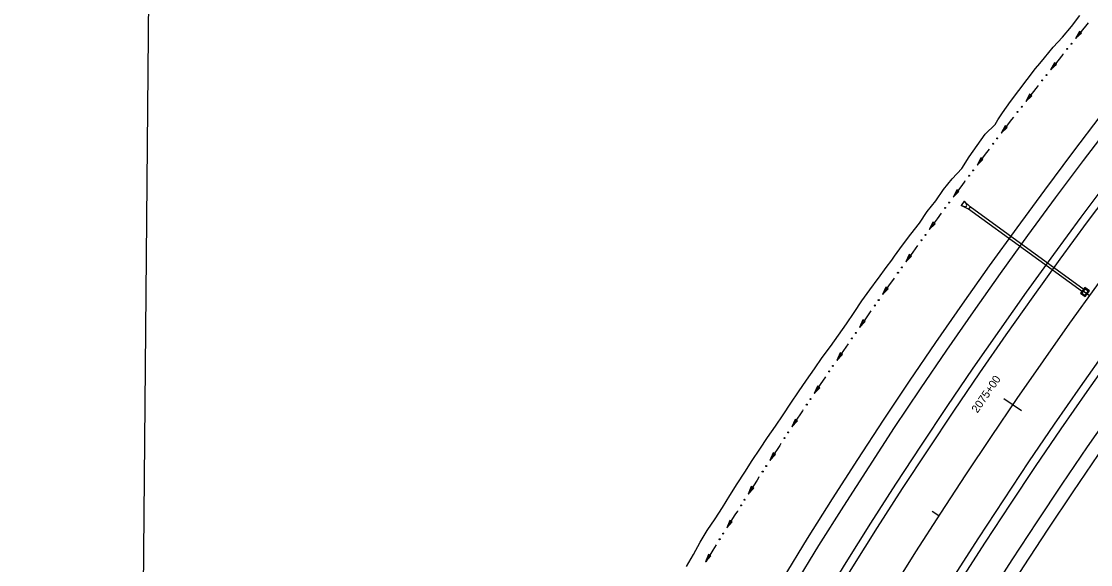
# Model space of a CAD drawing. Extents: x 1611108 to 1749517, y 619561 to 797725.
# Drawn here: x 1713533 to 1714335, y 764266 to 764673 of the extents above; entities that cross this region are included whole.
import ezdxf

# ---------------------------------------------------------------- set-up
doc = ezdxf.new("R2010")
doc.units = 0
for name, color, linetype in [('R_Ditch', 7, 'Continuous'), ('R_Drainage', 7, 'Continuous'), ('R_Horz Alg', 7, 'Continuous'), ('R_Horz Alg Annot', 7, 'Continuous'), ('R_Horz Alg Stationing', 7, 'Continuous'), ('R_Proposed Const Limits', 7, 'Continuous'), ('R_Proposed Road', 7, 'Continuous')]:
    doc.layers.add(name, color=color, linetype=linetype)

msp = doc.modelspace()

# ---------------------------------------------------------------- linework, layer by layer
at = {"layer": 'R_Ditch'}
for p, q in [((1714326.16, 764665.53), (1714323.23, 764660.19)), ((1714326.16, 764665.53), (1714323.23, 764660.19)), ((1714323.23, 764660.19), (1714327.81, 764664.21)), ((1714323.23, 764660.19), (1714327.81, 764664.21)), ((1714327.81, 764664.21), (1714326.16, 764665.53)), ((1714327.81, 764664.21), (1714326.16, 764665.53)), ((1714307.4, 764642.07), (1714304.51, 764636.7)), ((1714307.4, 764642.07), (1714304.51, 764636.7)), ((1714304.51, 764636.7), (1714309.06, 764640.75)), ((1714304.51, 764636.7), (1714309.06, 764640.75)), ((1714309.06, 764640.75), (1714307.4, 764642.07)), ((1714309.06, 764640.75), (1714307.4, 764642.07)), ((1714288.81, 764618.46), (1714285.97, 764613.07)), ((1714288.81, 764618.46), (1714285.97, 764613.07)), ((1714290.48, 764617.16), (1714288.81, 764618.46)), ((1714290.48, 764617.16), (1714288.81, 764618.46)), ((1714285.97, 764613.07), (1714290.48, 764617.16)), ((1714285.97, 764613.07), (1714290.48, 764617.16)), ((1714270.42, 764594.7), (1714267.6, 764589.3)), ((1714270.42, 764594.7), (1714267.6, 764589.3)), ((1714272.09, 764593.41), (1714270.42, 764594.7)), ((1714272.09, 764593.41), (1714270.42, 764594.7)), ((1714267.6, 764589.3), (1714272.09, 764593.41)), ((1714267.6, 764589.3), (1714272.09, 764593.41)), ((1714252.2, 764570.81), (1714249.42, 764565.39)), ((1714252.2, 764570.81), (1714249.42, 764565.39)), ((1714253.88, 764569.54), (1714252.2, 764570.81)), ((1714253.88, 764569.54), (1714252.2, 764570.81)), ((1714249.42, 764565.39), (1714253.88, 764569.54)), ((1714249.42, 764565.39), (1714253.88, 764569.54)), ((1714234.16, 764546.79), (1714231.42, 764541.34)), ((1714234.16, 764546.79), (1714231.42, 764541.34)), ((1714235.85, 764545.52), (1714234.16, 764546.79)), ((1714235.85, 764545.52), (1714234.16, 764546.79)), ((1714231.42, 764541.34), (1714235.85, 764545.52)), ((1714231.42, 764541.34), (1714235.85, 764545.52)), ((1714216.3, 764522.62), (1714213.61, 764517.16)), ((1714216.3, 764522.62), (1714213.61, 764517.16)), ((1714218.01, 764521.37), (1714216.3, 764522.62)), ((1714218.01, 764521.37), (1714216.3, 764522.62)), ((1714213.61, 764517.16), (1714218.01, 764521.37)), ((1714213.61, 764517.16), (1714218.01, 764521.37)), ((1714198.63, 764498.32), (1714195.98, 764492.84)), ((1714198.63, 764498.32), (1714195.98, 764492.84)), ((1714200.35, 764497.08), (1714198.63, 764498.32)), ((1714200.35, 764497.08), (1714198.63, 764498.32)), ((1714195.98, 764492.84), (1714200.35, 764497.08)), ((1714195.98, 764492.84), (1714200.35, 764497.08)), ((1714181.14, 764473.89), (1714178.54, 764468.38)), ((1714181.14, 764473.89), (1714178.54, 764468.38)), ((1714178.54, 764468.38), (1714182.87, 764472.66)), ((1714178.54, 764468.38), (1714182.87, 764472.66)), ((1714182.87, 764472.66), (1714181.14, 764473.89)), ((1714182.87, 764472.66), (1714181.14, 764473.89)), ((1714163.84, 764449.32), (1714161.28, 764443.8)), ((1714163.84, 764449.32), (1714161.28, 764443.8)), ((1714161.28, 764443.8), (1714165.58, 764448.11)), ((1714161.28, 764443.8), (1714165.58, 764448.11)), ((1714165.58, 764448.11), (1714163.84, 764449.32)), ((1714165.58, 764448.11), (1714163.84, 764449.32)), ((1714146.73, 764424.63), (1714144.21, 764419.08)), ((1714146.73, 764424.63), (1714144.21, 764419.08)), ((1714144.21, 764419.08), (1714148.47, 764423.43)), ((1714144.21, 764419.08), (1714148.47, 764423.43)), ((1714148.47, 764423.43), (1714146.73, 764424.63)), ((1714148.47, 764423.43), (1714146.73, 764424.63)), ((1714129.8, 764399.8), (1714127.33, 764394.23)), ((1714129.8, 764399.8), (1714127.33, 764394.23)), ((1714127.33, 764394.23), (1714131.56, 764398.62)), ((1714127.33, 764394.23), (1714131.56, 764398.62)), ((1714131.56, 764398.62), (1714129.8, 764399.8)), ((1714131.56, 764398.62), (1714129.8, 764399.8)), ((1714113.07, 764374.85), (1714110.64, 764369.26)), ((1714113.07, 764374.85), (1714110.64, 764369.26)), ((1714110.64, 764369.26), (1714114.83, 764373.68)), ((1714110.64, 764369.26), (1714114.83, 764373.68)), ((1714114.83, 764373.68), (1714113.07, 764374.85)), ((1714114.83, 764373.68), (1714113.07, 764374.85)), ((1714096.53, 764349.76), (1714094.14, 764344.16)), ((1714096.53, 764349.76), (1714094.14, 764344.16)), ((1714094.14, 764344.16), (1714098.3, 764348.61)), ((1714094.14, 764344.16), (1714098.3, 764348.61)), ((1714098.3, 764348.61), (1714096.53, 764349.76)), ((1714098.3, 764348.61), (1714096.53, 764349.76)), ((1714080.2, 764324.54), (1714077.85, 764318.92)), ((1714080.2, 764324.54), (1714077.85, 764318.92)), ((1714077.85, 764318.92), (1714081.98, 764323.4)), ((1714077.85, 764318.92), (1714081.98, 764323.4)), ((1714081.98, 764323.4), (1714080.2, 764324.54)), ((1714081.98, 764323.4), (1714080.2, 764324.54)), ((1714064.07, 764299.19), (1714061.77, 764293.55)), ((1714064.07, 764299.19), (1714061.77, 764293.55)), ((1714061.77, 764293.55), (1714065.86, 764298.06)), ((1714061.77, 764293.55), (1714065.86, 764298.06)), ((1714065.86, 764298.06), (1714064.07, 764299.19)), ((1714065.86, 764298.06), (1714064.07, 764299.19)), ((1714048.15, 764273.71), (1714045.89, 764268.05)), ((1714048.15, 764273.71), (1714045.89, 764268.05)), ((1714049.95, 764272.6), (1714048.15, 764273.71)), ((1714049.95, 764272.6), (1714048.15, 764273.71)), ((1714045.89, 764268.05), (1714049.95, 764272.6)), ((1714045.89, 764268.05), (1714049.95, 764272.6))]:
    msp.add_line(p, q, dxfattribs=at)
for points in [[(1714332.64, 764671.87), (1714326.52, 764664.29), (1714323.23, 764660.19)], [(1714332.64, 764671.87), (1714326.52, 764664.29), (1714323.23, 764660.19)], [(1714332.67, 764671.9), (1714332.64, 764671.87)], [(1714332.67, 764671.9), (1714332.64, 764671.87)], [(1714313.83, 764648.45), (1714313.61, 764648.17), (1714307.18, 764640.08), (1714304.51, 764636.7)], [(1714313.83, 764648.45), (1714313.61, 764648.17), (1714307.18, 764640.08), (1714304.51, 764636.7)], [(1714313.86, 764648.48), (1714313.83, 764648.45)], [(1714313.86, 764648.48), (1714313.83, 764648.45)], [(1714295.2, 764624.89), (1714294.39, 764623.86), (1714288.03, 764615.73), (1714285.97, 764613.07)], [(1714295.2, 764624.89), (1714294.39, 764623.86), (1714288.03, 764615.73), (1714285.97, 764613.07)], [(1714295.22, 764624.92), (1714295.2, 764624.89)], [(1714295.22, 764624.92), (1714295.2, 764624.89)], [(1714276.75, 764601.19), (1714275.37, 764599.41), (1714269.07, 764591.22), (1714267.6, 764589.3)], [(1714276.75, 764601.19), (1714275.37, 764599.41), (1714269.07, 764591.22), (1714267.6, 764589.3)], [(1714276.77, 764601.22), (1714276.75, 764601.19)], [(1714276.77, 764601.22), (1714276.75, 764601.19)], [(1714258.48, 764577.35), (1714256.54, 764574.8), (1714250.3, 764566.56), (1714249.42, 764565.39)], [(1714258.48, 764577.35), (1714256.54, 764574.8), (1714250.3, 764566.56), (1714249.42, 764565.39)], [(1714258.5, 764577.38), (1714258.48, 764577.35)], [(1714258.5, 764577.38), (1714258.48, 764577.35)], [(1714240.39, 764553.37), (1714237.9, 764550.04), (1714231.73, 764541.75), (1714231.42, 764541.34)], [(1714240.39, 764553.37), (1714237.9, 764550.04), (1714231.73, 764541.75), (1714231.42, 764541.34)], [(1714240.41, 764553.4), (1714240.39, 764553.37)], [(1714240.41, 764553.4), (1714240.39, 764553.37)], [(1714222.48, 764529.25), (1714219.45, 764525.13), (1714213.61, 764517.16)], [(1714222.48, 764529.25), (1714219.45, 764525.13), (1714213.61, 764517.16)], [(1714222.51, 764529.28), (1714222.48, 764529.25)], [(1714222.51, 764529.28), (1714222.48, 764529.25)], [(1714204.76, 764505), (1714201.2, 764500.08), (1714195.98, 764492.84)], [(1714204.76, 764505), (1714201.2, 764500.08), (1714195.98, 764492.84)], [(1714204.78, 764505.03), (1714204.76, 764505)], [(1714204.78, 764505.03), (1714204.76, 764505)], [(1714187.22, 764480.61), (1714183.14, 764474.88), (1714178.54, 764468.38)], [(1714187.22, 764480.61), (1714183.14, 764474.88), (1714178.54, 764468.38)], [(1714187.25, 764480.64), (1714187.22, 764480.61)], [(1714187.25, 764480.64), (1714187.22, 764480.61)], [(1714169.87, 764456.09), (1714165.29, 764449.54), (1714161.28, 764443.8)], [(1714169.87, 764456.09), (1714165.29, 764449.54), (1714161.28, 764443.8)], [(1714169.89, 764456.12), (1714169.87, 764456.09)], [(1714169.89, 764456.12), (1714169.87, 764456.09)], [(1714152.71, 764431.44), (1714147.62, 764424.06), (1714144.21, 764419.08)], [(1714152.71, 764431.44), (1714147.62, 764424.06), (1714144.21, 764419.08)], [(1714152.73, 764431.47), (1714152.71, 764431.44)], [(1714152.73, 764431.47), (1714152.71, 764431.44)], [(1714135.73, 764406.66), (1714130.16, 764398.44), (1714127.33, 764394.23)], [(1714135.73, 764406.66), (1714130.16, 764398.44), (1714127.33, 764394.23)], [(1714135.75, 764406.69), (1714135.73, 764406.66)], [(1714135.75, 764406.69), (1714135.73, 764406.66)], [(1714118.95, 764381.75), (1714118.63, 764381.28), (1714112.9, 764372.68), (1714110.64, 764369.26)], [(1714118.95, 764381.75), (1714118.63, 764381.28), (1714112.9, 764372.68), (1714110.64, 764369.26)], [(1714118.97, 764381.78), (1714118.95, 764381.75)], [(1714118.97, 764381.78), (1714118.95, 764381.75)], [(1714102.35, 764356.71), (1714101.51, 764355.43), (1714095.85, 764346.78), (1714094.14, 764344.16)], [(1714102.35, 764356.71), (1714101.51, 764355.43), (1714095.85, 764346.78), (1714094.14, 764344.16)], [(1714102.37, 764356.74), (1714102.35, 764356.71)], [(1714102.37, 764356.74), (1714102.35, 764356.71)], [(1714085.96, 764331.54), (1714084.6, 764329.43), (1714079.01, 764320.73), (1714077.85, 764318.92)], [(1714085.96, 764331.54), (1714084.6, 764329.43), (1714079.01, 764320.73), (1714077.85, 764318.92)], [(1714085.98, 764331.57), (1714085.96, 764331.54)], [(1714085.98, 764331.57), (1714085.96, 764331.54)], [(1714069.78, 764306.23), (1714067.9, 764303.29), (1714062.39, 764294.54), (1714061.77, 764293.55)], [(1714069.78, 764306.23), (1714067.9, 764303.29), (1714062.39, 764294.54), (1714061.77, 764293.55)], [(1714069.8, 764306.27), (1714069.78, 764306.23)], [(1714069.8, 764306.27), (1714069.78, 764306.23)], [(1714053.8, 764280.8), (1714051.43, 764277), (1714045.99, 764268.21), (1714045.89, 764268.05)], [(1714053.8, 764280.8), (1714051.43, 764277), (1714045.99, 764268.21), (1714045.89, 764268.05)], [(1714053.82, 764280.83), (1714053.8, 764280.8)], [(1714053.82, 764280.83), (1714053.8, 764280.8)]]:
    msp.add_lwpolyline(points, dxfattribs=at)
for centre in [(1714317, 764652.35), (1714317, 764652.35), (1714320.12, 764656.27), (1714320.12, 764656.27), (1714298.33, 764628.82), (1714298.33, 764628.82), (1714301.43, 764632.75), (1714301.43, 764632.75), (1714279.85, 764605.14), (1714279.85, 764605.14), (1714282.92, 764609.1), (1714282.92, 764609.1), (1714261.55, 764581.32), (1714261.55, 764581.32), (1714264.59, 764585.3), (1714264.59, 764585.3), (1714243.43, 764557.36), (1714243.43, 764557.36), (1714246.44, 764561.37), (1714246.44, 764561.37), (1714225.49, 764533.27), (1714225.49, 764533.27), (1714228.47, 764537.3), (1714228.47, 764537.3), (1714207.74, 764509.04), (1714207.74, 764509.04), (1714210.69, 764513.09), (1714210.69, 764513.09), (1714190.17, 764484.67), (1714190.17, 764484.67), (1714193.09, 764488.75), (1714193.09, 764488.75), (1714172.79, 764460.18), (1714172.79, 764460.18), (1714175.68, 764464.27), (1714175.68, 764464.27), (1714155.6, 764435.55), (1714155.6, 764435.55), (1714158.45, 764439.67), (1714158.45, 764439.67), (1714138.59, 764410.79), (1714138.59, 764410.79), (1714141.41, 764414.93), (1714141.41, 764414.93), (1714121.77, 764385.9), (1714121.77, 764385.9), (1714124.56, 764390.06), (1714124.56, 764390.06), (1714107.9, 764365.07), (1714107.9, 764365.07), (1714105.14, 764360.88), (1714105.14, 764360.88), (1714091.44, 764339.94), (1714091.44, 764339.94), (1714088.72, 764335.74), (1714088.72, 764335.74), (1714075.19, 764314.68), (1714075.19, 764314.68), (1714072.5, 764310.45), (1714072.5, 764310.45), (1714056.48, 764285.04), (1714056.48, 764285.04), (1714059.14, 764289.29), (1714059.14, 764289.29)]:
    msp.add_circle(centre, 0.375, dxfattribs=at)
at = {"layer": 'R_Drainage'}
for p, q in [((1714239.79, 764538.38), (1714237.44, 764535.14)), ((1714244.16, 764533.98), (1714239.79, 764538.38)), ((1714239.79, 764538.38), (1714241.54, 764536.02)), ((1714242.99, 764532.36), (1714237.44, 764535.14)), ((1714237.44, 764535.14), (1714240.23, 764534.22)), ((1714244.16, 764533.98), (1714242.99, 764532.36)), ((1714328.57, 764470.33), (1714242.99, 764532.36)), ((1714329.75, 764471.95), (1714244.16, 764533.98))]:
    msp.add_line(p, q, dxfattribs=at)
for points in [[(1714327.05, 764469.37), (1714330.56, 764466.83), (1714333.69, 764471.14), (1714330.18, 764473.69)], [(1714327.98, 764469.52), (1714330.41, 764467.76), (1714332.76, 764470.99), (1714330.33, 764472.76)]]:
    msp.add_lwpolyline(points, close=True, dxfattribs=at)
msp.add_arc((1714240.6, 764535.32), 1.17, 251.59517, 36.53533, dxfattribs=at)
at = {"layer": 'R_Horz Alg'}
msp.add_arc((1717426.61, 762226.09), 3819.72, 112.5, 179.5, dxfattribs=at)
at = {"layer": 'R_Horz Alg Annot'}
msp.add_line((1713629.09, 764787.55), (1713607.03, 762259.43), dxfattribs=at)
at = {"layer": 'R_Horz Alg Stationing'}
for points in [[(1714328.97, 764471.27), (1714333.83, 764467.75)], [(1714269.61, 764390.54), (1714282.81, 764381.5)], [(1714215.72, 764306.07), (1714220.75, 764302.81)]]:
    msp.add_lwpolyline(points, dxfattribs=at)
at = {"layer": 'R_Proposed Const Limits'}
msp.add_lwpolyline([(1714031.69, 764264.73), (1714036.8, 764273.76), (1714041.93, 764282.78), (1714047.14, 764291.74), (1714053.02, 764300.3), (1714058.67, 764308.99), (1714064.17, 764317.79), (1714069.71, 764326.55), (1714075.28, 764335.29), (1714080.95, 764343.97), (1714086.66, 764352.62), (1714092.36, 764361.28), (1714098.25, 764369.82), (1714104.13, 764378.36), (1714109.87, 764386.99), (1714115.63, 764395.6), (1714121.51, 764404.14), (1714127.46, 764412.63), (1714133.43, 764421.11), (1714139.54, 764429.48), (1714145.58, 764437.9), (1714151.5, 764446.41), (1714157.39, 764454.93), (1714163.11, 764463.57), (1714169.13, 764471.99), (1714175.25, 764480.36), (1714175.49, 764480.68), (1714181.4, 764488.7), (1714185.42, 764494.03), (1714187.57, 764497.02), (1714193.64, 764505.41), (1714199.83, 764513.72), (1714206.33, 764521.8), (1714211.98, 764530.49), (1714218.47, 764538.57), (1714224.33, 764547.11), (1714230.86, 764555.17), (1714238.01, 764562.76), (1714243.42, 764571.63), (1714249.45, 764580.05), (1714255.56, 764588.4), (1714262.88, 764595.86), (1714265.03, 764599.18), (1714268.53, 764604.56), (1714274.49, 764613.03), (1714280.8, 764621.23), (1714287.06, 764629.47), (1714293.36, 764637.69), (1714296.43, 764641.48), (1714299.89, 764645.73), (1714306.53, 764653.68), (1714313.59, 764661.29), (1714320.24, 764669.23), (1714326.5, 764677.47)], dxfattribs=at)
at = {"layer": 'R_Proposed Road'}
for radius in [3893.72, 3883.72, 3859.72, 3853.72, 3785.72, 3779.72, 3755.72, 3745.72]:
    msp.add_arc((1717426.61, 762226.09), radius, 112.5, 179.5, dxfattribs=at)

# ---------------------------------------------------------------- texts
at = {"layer": 'R_Horz Alg Stationing'}
msp.add_text('2075+00', height=6, rotation=55.56525, dxfattribs=at).set_placement((1714249.69, 764379.17))

doc.saveas('drawing.dxf')
